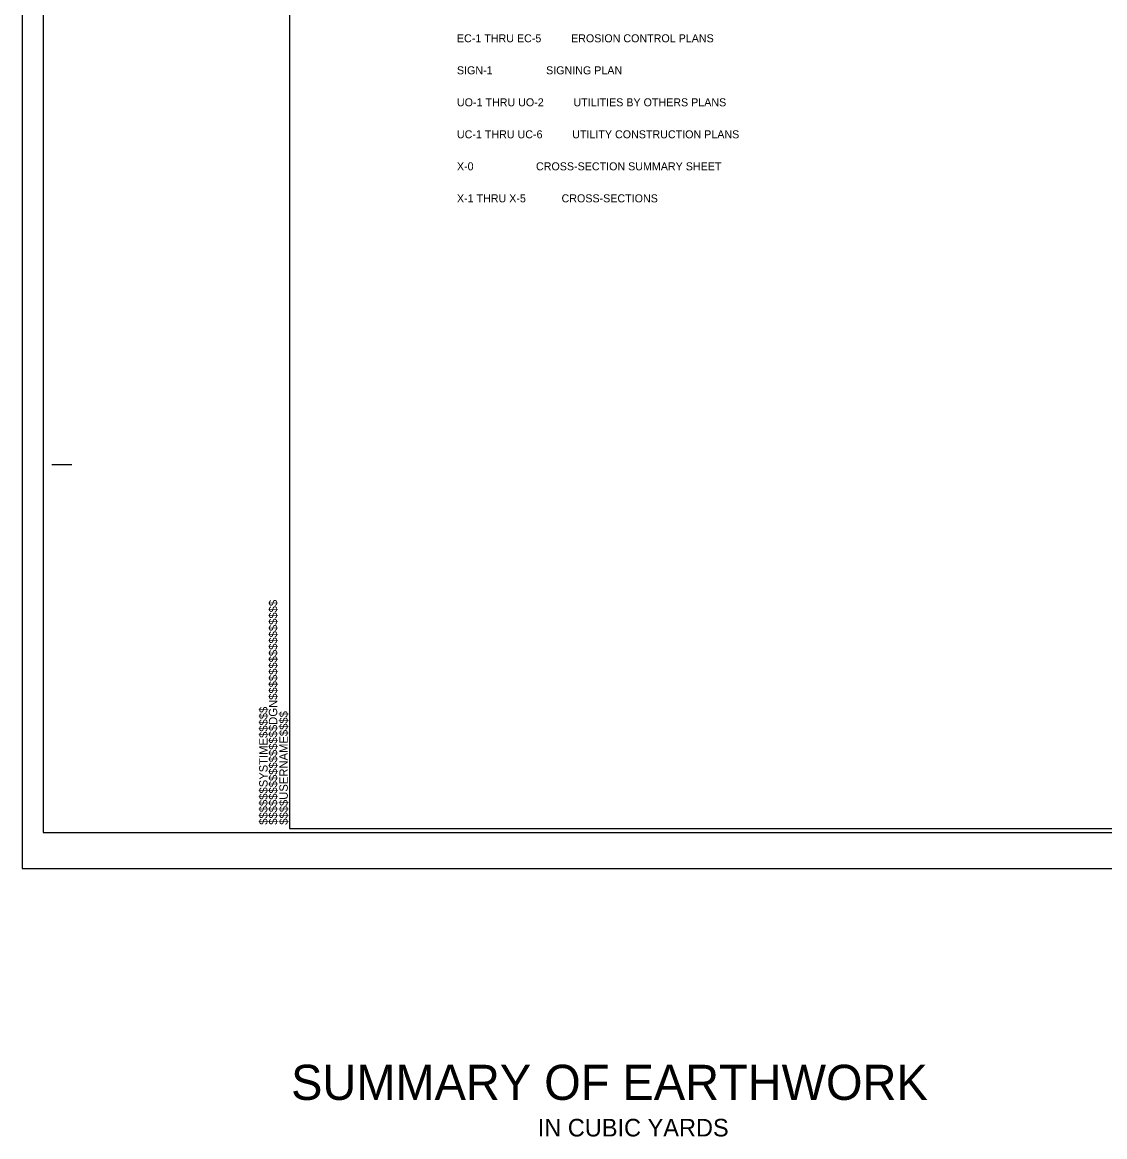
# Model space of a CAD drawing. Extents: x 1728265 to 1732106, y 539919 to 543766.
# Drawn here: x 1729453 to 1730130, y 542383 to 543079 of the extents above; entities that cross this region are included whole.
import ezdxf

# ---------------------------------------------------------------- set-up
doc = ezdxf.new("R2010")
doc.units = 0
for name, color, linetype in [('Default', 7, 'Continuous'), ('Sheet Cutting Line CELL', 7, 'Continuous'), ('Sheet Plot Border Inside CELL', 7, 'Continuous'), ('Sheet Plot Border Outside CELL', 7, 'Continuous'), ('Sheet Summary CELL', 7, 'Continuous')]:
    doc.layers.add(name, color=color, linetype=linetype)

msp = doc.modelspace()

# ---------------------------------------------------------------- linework, layer by layer
at = {"layer": 'Sheet Cutting Line CELL'}
for p, q in [((1729453.34, 543650.62), (1729453.34, 542550.62)), ((1729453.34, 542550.62), (1731137.34, 542550.62))]:
    msp.add_line(p, q, dxfattribs=at)
at = {"layer": 'Sheet Plot Border Inside CELL'}
msp.add_lwpolyline([(1731132.84, 543628.17), (1729466.34, 543628.17), (1729466.34, 542573.07), (1731132.84, 542573.07)], close=True, dxfattribs=at)
at = {"layer": 'Sheet Plot Border Outside CELL'}
msp.add_lwpolyline([(1731137.34, 543650.62), (1729453.34, 543650.62), (1729453.34, 542550.62), (1731137.34, 542550.62)], close=True, dxfattribs=at)
at = {"layer": 'Sheet Summary CELL'}
for p, q in [((1729471.84, 542803.12), (1729484.34, 542803.12)), ((1729620.34, 542575.62), (1729620.34, 542575.62)), ((1729620.34, 542575.62), (1729620.34, 542575.62)), ((1729620.34, 542575.62), (1729620.34, 542575.62)), ((1729620.34, 542575.62), (1729620.34, 542575.62)), ((1729620.34, 542575.62), (1729620.34, 542575.62)), ((1729620.34, 542575.62), (1729620.34, 542575.62))]:
    msp.add_line(p, q, dxfattribs=at)
msp.add_lwpolyline([(1731120.34, 543625.62), (1729620.34, 543625.62), (1729620.34, 542575.62), (1731120.34, 542575.62)], close=True, dxfattribs=at)
msp.add_lwpolyline([(1729757.84, 542575.62), (1729757.84, 542575.62)], dxfattribs=at)

# ---------------------------------------------------------------- texts
at = {"layer": 'Default'}
for s, p in [('EC-1 THRU EC-5          EROSION CONTROL PLANS', (1729724.98, 543066.93)), ('SIGN-1                  SIGNING PLAN', (1729724.98, 543046.93)), ('UO-1 THRU UO-2          UTILITIES BY OTHERS PLANS', (1729724.98, 543026.93)), ('UC-1 THRU UC-6          UTILITY CONSTRUCTION PLANS', (1729724.98, 543006.93)), ('X-0                     CROSS-SECTION SUMMARY SHEET', (1729724.98, 542986.93)), ('X-1 THRU X-5            CROSS-SECTIONS', (1729724.98, 542966.93))]:
    msp.add_text(s, height=5, dxfattribs=at).set_placement(p)
at = {"layer": 'Sheet Summary CELL'}
for s, p in [('$$$$$$$$$$$$$$$$DGN$$$$$$$$$$$$$$$$', (1729612.69, 542577.98)), ('$$$$$$SYSTIME$$$$$', (1729606.64, 542577.98)), ('$$$$USERNAME$$$$', (1729619.27, 542578))]:
    msp.add_text(s, height=5.25, rotation=90, dxfattribs=at).set_placement(p)
for s, height, p in [('SUMMARY OF EARTHWORK', 21.9501, (1729621.34, 542406.07)), ('IN CUBIC YARDS', 10.9998, (1729775.49, 542383.22))]:
    msp.add_text(s, height=height, dxfattribs=at).set_placement(p)

doc.saveas('drawing.dxf')
